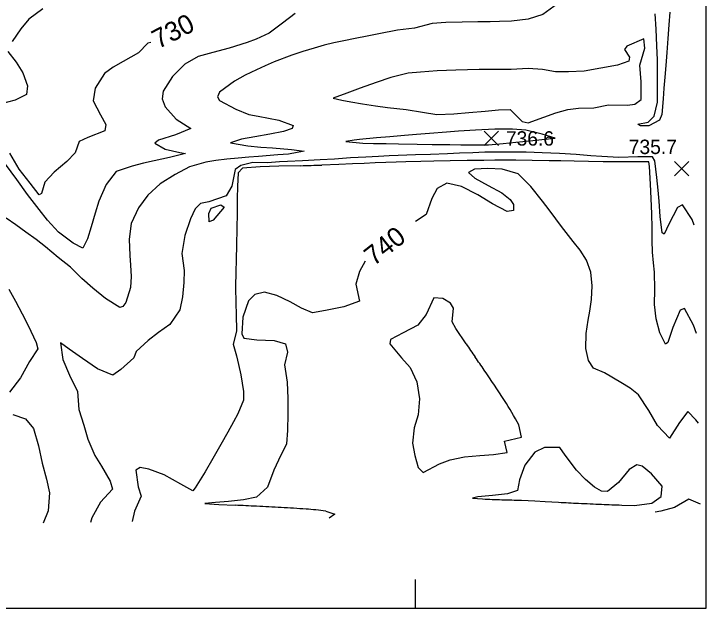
# Model space of a CAD drawing. Extents: x 2566079 to 2571326, y 424054 to 426896.
# Drawn here: x 2570581 to 2571303, y 424077 to 424697 of the extents above; entities that cross this region are included whole.
import ezdxf

# ---------------------------------------------------------------- set-up
doc = ezdxf.new("R2010")
doc.units = 0
for name, color, linetype in [('Contour_ADS_Label_Major', 7, 'Continuous'), ('Contour_ADS_Major', 7, 'Continuous'), ('Contour_ADS_Minor', 7, 'Continuous'), ('Contour_ADS_Spot_Elevation', 7, 'Continuous'), ('Contour_ADS_State_Plane_Border', 7, 'Continuous')]:
    doc.layers.add(name, color=color, linetype=linetype)

# ---------------------------------------------------------------- blocks, each defined once
blk = doc.blocks.new('S750')
at = {"layer": 'Contour_ADS_Spot_Elevation'}
for p, q in [((-0.5, 0.498), (0.5, -0.498)), ((-0.498, -0.5), (0.498, 0.5))]:
    blk.add_line(p, q, dxfattribs=at)

msp = doc.modelspace()

# ---------------------------------------------------------------- linework, layer by layer
at = {"layer": 'Contour_ADS_Major'}
for points in [[(2570723.79, 424667.45), (2570720.76, 424666.42), (2570711.11, 424656.51), (2570695.2, 424647.29), (2570684.68, 424641.71), (2570675.45, 424635.09), (2570665.96, 424619.74), (2570663.69, 424606.26), (2570671.4, 424591.95), (2570677.07, 424581.67), (2570675.85, 424575.09), (2570658.36, 424568.14), (2570649.14, 424563.93), (2570645.04, 424552.02), (2570636.29, 424543.2), (2570622.96, 424531.96), (2570613.45, 424521.45), (2570609.78, 424509.6), (2570607.6, 424508.49), (2570597.98, 424520.4), (2570586.53, 424535), (2570576.99, 424551.66)], [(2571295.12, 424269.96), (2571292.04, 424273.63), (2571283.9, 424282.22), (2571275.1, 424270.87), (2571264.55, 424254.34), (2571252.13, 424267.82), (2571243.32, 424283.47), (2571232.32, 424299.81), (2571223.58, 424306.79), (2571214.01, 424312.62), (2571196.83, 424322.76), (2571185.48, 424327.47), (2571180.13, 424335.47), (2571177.46, 424348.16), (2571177.74, 424363.51), (2571179.93, 424377.51), (2571181.58, 424386.83), (2571183.33, 424399.3), (2571184.11, 424413.56), (2571182.62, 424427.68), (2571178.04, 424440.08), (2571171.46, 424450.68), (2571164.43, 424459.77), (2571152.27, 424475.35), (2571146.17, 424483.45), (2571139.38, 424492.55), (2571132.35, 424501.9), (2571120.15, 424517.18), (2571106.8, 424530.3), (2571090.34, 424535.1), (2571075.45, 424535.94), (2571061.41, 424535.07), (2571055.25, 424531.8), (2571061.62, 424525.79), (2571075.58, 424518.14), (2571089.8, 424510.3), (2571098.51, 424503.52), (2571102.18, 424498.13), (2571102.13, 424491.92), (2571095.39, 424491.07), (2571080.08, 424499.08), (2571064.95, 424508.31), (2571047.69, 424517.14), (2571032.48, 424520.5), (2571022.48, 424515.05), (2571016.78, 424504.4), (2571010.86, 424487.68), (2570999.69, 424480.38)], [(2570947.34, 424439.1), (2570941.56, 424428.41), (2570937.72, 424414.98), (2570941.49, 424397.56), (2570925.12, 424391.6), (2570906.16, 424387.53), (2570892.63, 424385.33), (2570880.94, 424389.98), (2570869.2, 424396.56), (2570855.3, 424403.35), (2570842.24, 424406.81), (2570832.44, 424404.4), (2570825.86, 424397.64), (2570819.73, 424380.72), (2570818.84, 424363.26), (2570820.73, 424358.69), (2570834.29, 424357.23), (2570852.51, 424356.35), (2570864.42, 424352.94), (2570866.37, 424344.16), (2570863.18, 424330.9), (2570865.94, 424313), (2570866.67, 424295.78), (2570866.87, 424279.86), (2570866.23, 424262.35), (2570865.24, 424248.44), (2570856.91, 424231.45), (2570852.16, 424221.19), (2570845.39, 424203.19), (2570834.05, 424193.05), (2570820.66, 424190.21), (2570804.91, 424188.44), (2570791.45, 424187.43), (2570780.16, 424186.48), (2570794.96, 424185.22), (2570811.71, 424184.48)], [(2570906.31, 424178.27), (2570915.63, 424175.16), (2570909.83, 424171.1)]]:
    msp.add_lwpolyline(points, dxfattribs=at)
for centre, radius, start, end in [((2570569.1, 418808), 5381.95, 87.17709, 87.41636), ((2570647.24, 420354.5), 3833.48, 86.82081, 87.20515), ((2570780.27, 422694.86), 1489.34, 85.94025, 86.93742), ((2570863.79, 423877.64), 303.63, 81.94905, 85.85923)]:
    msp.add_arc(centre, radius, start, end, dxfattribs=at)
at = {"layer": 'Contour_ADS_Minor'}
msp.add_line((2571110.45, 424189.7), (2571110.45, 424189.7), dxfattribs=at)
for points in [[(2571148.09, 424707.47), (2571132.7, 424696.56), (2571117.21, 424691.47), (2571100.13, 424689.61), (2571087.44, 424689.19), (2571077.82, 424688.97), (2571064.86, 424688.74), (2571048.43, 424688.48), (2571031.41, 424688.02), (2571017.4, 424687.19), (2570998.81, 424682.35), (2570981.19, 424680), (2570961.6, 424676.41), (2570949.57, 424674.05), (2570937.03, 424671.54), (2570925.12, 424669.08), (2570914.58, 424666.79), (2570904.63, 424664.39), (2570894.13, 424661.47), (2570882.46, 424657.81), (2570871.07, 424654), (2570852.54, 424647.11), (2570843.26, 424643.09), (2570833.92, 424638.83), (2570822.41, 424633.25), (2570810.98, 424627.08), (2570795.51, 424615.37), (2570793.29, 424610.55), (2570795.39, 424606.72), (2570812.39, 424597.72), (2570826.15, 424592.3), (2570835.75, 424590.26), (2570846.55, 424588.41), (2570857.36, 424586.32), (2570872.24, 424580.67), (2570871.3, 424577.54), (2570862.34, 424574.51), (2570848.06, 424571.66), (2570832.22, 424569.01), (2570818.38, 424566.59), (2570807, 424562.46), (2570825.08, 424559.36), (2570838.62, 424558.22), (2570850.74, 424557.32), (2570870.39, 424555.77), (2570883.62, 424553.87), (2570867.57, 424550.85), (2570856.18, 424549.96), (2570836.25, 424548.41), (2570826.22, 424547.62), (2570815.02, 424546.73), (2570803.21, 424545.63), (2570791.65, 424544.21), (2570781.11, 424542.38), (2570764.21, 424537.71), (2570749.23, 424529.66), (2570733.49, 424519.67), (2570720.65, 424508.14), (2570711.13, 424494.95), (2570703.23, 424478.61), (2570701.42, 424462.04), (2570702.09, 424445.18), (2570702.82, 424434.88), (2570703.25, 424423.08)], [(2570874.36, 424697.51), (2570861.12, 424687.37), (2570847.16, 424677.18), (2570833.61, 424670.75), (2570824.29, 424667.27), (2570805.4, 424661.23), (2570788.59, 424656.81), (2570773.28, 424652.52), (2570759.32, 424644.6), (2570746.55, 424631.93), (2570736.66, 424616.53), (2570735.72, 424608.35), (2570738.8, 424600.25), (2570750.22, 424587.25), (2570765.53, 424577.46), (2570749.58, 424571.12), (2570731.75, 424565.5), (2570728.04, 424562.23), (2570738.81, 424556.17), (2570754.25, 424552.62), (2570760.12, 424551.54), (2570743.51, 424547.45), (2570727.32, 424543.76), (2570716.31, 424541.28), (2570704.37, 424538.36), (2570687.74, 424532.53), (2570677.18, 424519.25), (2570669.57, 424501.66), (2570665.88, 424489.26), (2570661.67, 424474.94), (2570657.97, 424462.6), (2570652.92, 424452.81), (2570642.82, 424457.77), (2570627.63, 424469.53), (2570616.09, 424481.93), (2570607.39, 424492.91), (2570595.46, 424508.65), (2570584.2, 424524.51), (2570572.5, 424540.43)], [(2570611.35, 424702.58), (2570596.72, 424691.72), (2570588.33, 424681.45), (2570579.32, 424668.17)], [(2571264.95, 424699.04), (2571263.96, 424685.89), (2571262.94, 424671.32), (2571261.89, 424656.75), (2571260.82, 424643.33), (2571259.8, 424631.03), (2571258.91, 424619.52), (2571258.19, 424608.68), (2571256.74, 424592.27), (2571254.3, 424586.26), (2571243.08, 424580.25), (2571234.49, 424580.41), (2571231.62, 424582.16), (2571242.53, 424584.21), (2571248.88, 424590.37), (2571252.04, 424604.86), (2571252.1, 424622.7), (2571252.34, 424640.35), (2571252.08, 424649.16), (2571251.57, 424663.89), (2571250.78, 424681.35), (2571249.63, 424697.29)], [(2570574.71, 424657.99), (2570583.36, 424646.82), (2570590.56, 424635.8), (2570595.39, 424622.06), (2570594.09, 424612.99), (2570582.53, 424607.08), (2570565.93, 424602.92)], [(2571290.51, 424476.81), (2571288.36, 424482.78), (2571278.29, 424497.93), (2571273, 424495.03), (2571264.06, 424477.86), (2571259.3, 424467.19), (2571256.92, 424468.59), (2571255.1, 424485.75), (2571253.99, 424501.67), (2571252.94, 424513.34), (2571251.67, 424526.28), (2571249.28, 424543.84), (2571247.12, 424548.09), (2571231.81, 424548), (2571211.95, 424547.35), (2571194.14, 424548.24), (2571182.7, 424549.21), (2571167.42, 424550.38), (2571149.97, 424551.46), (2571132.03, 424552.23), (2571115.21, 424552.7), (2571101.13, 424552.95), (2571081.92, 424552.97), (2571072.2, 424552.72), (2571059.68, 424552.28), (2571045.9, 424551.76), (2571033.21, 424551.26), (2571015.44, 424550.6), (2570999.97, 424550.04), (2570981.94, 424549.38), (2570972.29, 424549), (2570961.38, 424548.5), (2570948.16, 424547.78), (2570932.17, 424546.8), (2570915.43, 424545.73), (2570900.56, 424544.78), (2570881.93, 424543.72), (2570866.48, 424543.08), (2570857.99, 424542.68), (2570845.42, 424541.88), (2570830.14, 424541.98), (2570817.66, 424539.05), (2570811.78, 424534.64), (2570808.18, 424517.37), (2570802.41, 424507.32), (2570784.28, 424501.21), (2570775.67, 424499.23), (2570770.24, 424493.64), (2570765.17, 424483.25), (2570759.4, 424466.04), (2570756.25, 424446.98), (2570758.71, 424429.52), (2570758.38, 424416.81), (2570756.94, 424401.83), (2570754, 424388.3), (2570743.59, 424373.12), (2570731.77, 424364.77), (2570721.17, 424356.38), (2570708.67, 424344.75), (2570706.25, 424338.15), (2570692.56, 424326.26), (2570684.29, 424320.1), (2570668.21, 424326.88), (2570652.57, 424337.48), (2570638.65, 424347.26), (2570629.66, 424353.77), (2570632.29, 424336.51), (2570639.05, 424320.3), (2570647.43, 424303.04), (2570648.94, 424284.52), (2570654.19, 424267.94), (2570658.36, 424253.3), (2570665.66, 424236.47), (2570672.62, 424225.13), (2570681.46, 424209.46), (2570684, 424201.36), (2570671.55, 424187.59), (2570662.3, 424171.38), (2570660.84, 424166.57)], [(2570880.1, 424538.77), (2570857.19, 424538.13), (2570837.95, 424537.59), (2570819.38, 424536.29), (2570815.08, 424531.28), (2570814.19, 424517.01), (2570814.01, 424504.66), (2570813.82, 424489.57), (2570813.57, 424472.96), (2570813.24, 424456.14), (2570812.88, 424440.63), (2570812.57, 424428.02), (2570812.34, 424412.31), (2570812.61, 424394.96), (2570812.84, 424383.96), (2570813.1, 424366.07), (2570809.91, 424352.46), (2570813.21, 424340.46), (2570815.38, 424331.24), (2570817.7, 424320.52), (2570820.66, 424303.23), (2570820.52, 424294.03), (2570814.69, 424279.98), (2570810.18, 424271.57), (2570804.21, 424260.78), (2570796.88, 424247.85), (2570788.52, 424233.38), (2570780.37, 424219.49), (2570770.2, 424202.74), (2570767.77, 424199.58), (2570755.1, 424206.62), (2570737.64, 424216.11), (2570721.95, 424222.18), (2570712.88, 424223.73), (2570708.16, 424220.99), (2570710.73, 424203.58), (2570713.8, 424194.08), (2570706.74, 424178.44), (2570704.35, 424167.36)], [(2571293.03, 424363.72), (2571289.82, 424372.47), (2571280.29, 424389.73), (2571275.74, 424387.88), (2571268.19, 424370.04), (2571262.94, 424354.32), (2571260.41, 424352.65), (2571254.65, 424364.36), (2571250.65, 424378.81), (2571248.98, 424394.05), (2571249.5, 424409.62), (2571249.11, 424427.75), (2571248.05, 424437.49), (2571247.12, 424448.63), (2571246.66, 424460.79), (2571246.47, 424474.08), (2571246.21, 424488.7), (2571245.65, 424504.45), (2571244.91, 424519.38), (2571243.83, 424538), (2571243.33, 424542.71), (2571223.62, 424542.62), (2571210.5, 424542.64), (2571195.61, 424542.77), (2571180.31, 424543.04), (2571165.4, 424543.39), (2571151.55, 424543.71), (2571139.38, 424543.95), (2571121.54, 424544.25), (2571104.43, 424544.48), (2571094.44, 424544.46), (2571082.64, 424544.4), (2571071.26, 424544.33), (2571053.75, 424544.22), (2571035.97, 424543.94), (2571018.83, 424543.56), (2571005.44, 424543.21), (2570989.71, 424542.8), (2570979.59, 424542.49), (2570968.88, 424542.12), (2570957.75, 424541.68), (2570946.24, 424541.19), (2570934.11, 424540.65), (2570919.97, 424540.07), (2570902.18, 424539.44)], [(2570703.25, 424423.08), (2570702.73, 424411.74), (2570697.94, 424395.87), (2570694.72, 424391.9), (2570691.55, 424390.67), (2570676.6, 424400.31), (2570663.24, 424411.06), (2570651.86, 424421), (2570639.96, 424433.04), (2570627.15, 424443.06), (2570613.95, 424454.22), (2570604.3, 424461.6), (2570593.67, 424469.41), (2570582.95, 424477.05), (2570572.95, 424483.92)], [(2570575.67, 424409.99), (2570582.7, 424397.36), (2570589.79, 424384.18), (2570595.99, 424371.98), (2570604.19, 424354.22), (2570605.93, 424347.61), (2570597.51, 424334.36), (2570588.13, 424317.28), (2570576.43, 424302.63)], [(2571052.65, 424352.76), (2571041.96, 424368.72), (2571038.17, 424375.8), (2571039.42, 424390.18), (2571036.2, 424395.32), (2571028.19, 424400.07), (2571019.01, 424400.81), (2571011.06, 424383.66), (2571011.06, 424383.66)], [(2571011.06, 424383.66), (2571002.17, 424372.24), (2570986.95, 424364.34), (2570973.87, 424357.32), (2570973.19, 424352.79), (2570985.31, 424338.37), (2570994.36, 424328.25), (2571001.2, 424313.26), (2571004.17, 424295.68), (2571002.78, 424278.93), (2570998.57, 424265.26), (2570996.84, 424249.19), (2570999.18, 424236.5), (2571002.69, 424223.77), (2571007.96, 424218.82), (2571024.73, 424227.84), (2571035.85, 424232.03), (2571050.83, 424234.85), (2571067.06, 424236.5), (2571081.14, 424237.52), (2571095.34, 424239.43), (2571092.59, 424251.31), (2571110.49, 424255.64), (2571107.47, 424268.25)], [(2570580.14, 424279.26), (2570593.09, 424274.55), (2570601.4, 424264.42), (2570606.91, 424246.59), (2570610.7, 424228.54), (2570615.07, 424211.66), (2570618.22, 424197.51), (2570616.83, 424178.63), (2570611.71, 424165.68)], [(2571214.94, 424184.67), (2571228.29, 424184.34), (2571246.38, 424186.54), (2571256.06, 424193.73), (2571256.96, 424204.5), (2571245.77, 424217.26), (2571236.36, 424225.4), (2571230.67, 424226.55), (2571222.65, 424221.81), (2571211.44, 424208.28), (2571199.9, 424198.87), (2571193.84, 424199.22), (2571186.45, 424203.46), (2571177.29, 424211.45), (2571167.91, 424221.19), (2571155.91, 424236.66), (2571150.24, 424244.79), (2571134.22, 424244.82), (2571124.35, 424239.89), (2571113.78, 424226.45), (2571108.34, 424211.16), (2571106.27, 424200.02), (2571095.63, 424196.33), (2571080.22, 424194.73), (2571064.97, 424193.24), (2571059.39, 424191.97), (2571069.83, 424191.01)], [(2571110.45, 424189.7), (2571124.33, 424189.13), (2571135.14, 424188.48), (2571148.99, 424187.64)], [(2571297, 424185.67), (2571284.95, 424190.84), (2571269.76, 424182.27), (2571255.74, 424178.24), (2571249.67, 424177.28)]]:
    msp.add_lwpolyline(points, dxfattribs=at)
for points in [[(2570922.95, 424607.04), (2570932.32, 424605.33), (2570944.62, 424603.23), (2570958.01, 424601.16), (2570970.79, 424599.5), (2570990.26, 424597.37), (2571007.2, 424594.43), (2571022.17, 424592.15), (2571039.99, 424592.77), (2571055.45, 424594.08), (2571072.37, 424595.66), (2571086.47, 424597.01), (2571098.6, 424597.21), (2571111.11, 424584.74), (2571117.46, 424583.5), (2571133.77, 424589.54), (2571146.21, 424593.85), (2571158.86, 424597.23), (2571169.92, 424598.71), (2571185.76, 424598.99), (2571201.21, 424602.36), (2571220.87, 424601.92), (2571228.52, 424603.06), (2571235.29, 424607.71), (2571235.16, 424626.15), (2571233.93, 424643.8), (2571238.94, 424661.39), (2571238.12, 424671.12), (2571220.22, 424663.49), (2571217.77, 424660.11), (2571223.13, 424652.02), (2571222.18, 424647.72), (2571210.44, 424643.7), (2571193.01, 424640.62), (2571175.58, 424637.49), (2571159.45, 424636.58), (2571145.99, 424636.79), (2571132.29, 424639.16), (2571117.35, 424640.16), (2571099.65, 424639.22), (2571089.4, 424639.02), (2571078.26, 424639.03), (2571066.37, 424639.05), (2571054.02, 424638.9), (2571041.99, 424638.58), (2571022.39, 424637.61), (2571005.23, 424636.36), (2570992.18, 424635.42), (2570974.16, 424630.88), (2570958.74, 424625.63), (2570942.01, 424619.56), (2570928.1, 424614.39), (2570913.86, 424609.07), (2570922.95, 424607.04)], [(2570936.08, 424565.46), (2570927.15, 424563.97), (2570945.08, 424562.4), (2570956.08, 424562.08), (2570969.25, 424561.78), (2570982.1, 424561.54), (2571001.51, 424561.24), (2571017.23, 424560.99), (2571035.72, 424560.71), (2571047.3, 424560.58), (2571059.02, 424560.51), (2571076.03, 424560.68), (2571091.27, 424561.95), (2571104.4, 424563.24), (2571119.16, 424564.68), (2571131.76, 424565.91), (2571145.61, 424567.34), (2571131.82, 424571.82), (2571114.85, 424575.68), (2571100.84, 424576.78), (2571082.42, 424576.71), (2571062.49, 424575.84), (2571044.76, 424574.73), (2571032.08, 424573.83), (2571014.29, 424572.35), (2571001, 424571.19), (2570988.24, 424570.11), (2570973.25, 424568.85), (2570959.28, 424567.66), (2570941.48, 424566.04), (2570936.08, 424565.46)], [(2570796.98, 424498.08), (2570800.23, 424495.51), (2570789.05, 424481.87), (2570784.84, 424480.01), (2570784.38, 424488.83), (2570786.92, 424494.45), (2570796.98, 424498.08)]]:
    msp.add_lwpolyline(points, close=True, dxfattribs=at)
for centre, radius, start, end in [((2570679.11, 431526.44), 6990.56, 271.647533, 271.828589), ((2572509.71, 425350.14), 1765.73, 214.39211, 214.93298), ((2569340.57, 423137.65), 2099.32, 34.45475, 34.90945), ((2569985.11, 423577.84), 1318.81, 32.88562, 34.52814), ((2570835.62, 424127.69), 306.04, 27.34182, 32.89567), ((2571137.46, 425802.69), 1613.09, 267.59716, 268.31405), ((2571270.55, 430093.57), 5906.04, 268.248189, 268.446661), ((2571302.1, 426955.18), 2771.78, 266.83342, 267.26727), ((2571342.44, 427721.05), 3538.69, 267.20611, 267.59526), ((2571291.44, 426466.48), 2283.1, 267.55284, 268.07973)]:
    msp.add_arc(centre, radius, start, end, dxfattribs=at)
at = {"layer": 'Contour_ADS_State_Plane_Border'}
msp.add_line((2571000, 424077.11), (2571000, 424107.11), dxfattribs=at)
msp.add_lwpolyline([(2566079.33, 424077.11), (2571302.93, 424077.11), (2571302.93, 426873.74), (2566079.33, 426873.74), (2566079.33, 424077.11)], close=True, dxfattribs=at)

# ---------------------------------------------------------------- block references
at = {"layer": 'Contour_ADS_Spot_Elevation', "xscale": 15, "yscale": 15}
for p in [(2571079.07, 424567.2), (2571277.35, 424535.67)]:
    msp.add_blockref('S750', p, dxfattribs=at)

# ---------------------------------------------------------------- texts
at = {"layer": 'Contour_ADS_Label_Major'}
for s, rotation, p in [('730', 27.01799, (2570731.55, 424660.18)), ('740', 38.25138, (2570956.37, 424433.49))]:
    msp.add_text(s, height=20, rotation=rotation, dxfattribs=at).set_placement(p)
at = {"layer": 'Contour_ADS_Spot_Elevation'}
for s, p in [('736.6', (2571094.07, 424559.7)), ('735.7', (2571222.22, 424550.92))]:
    msp.add_text(s, height=15, dxfattribs=at).set_placement(p)

doc.saveas('drawing.dxf')
